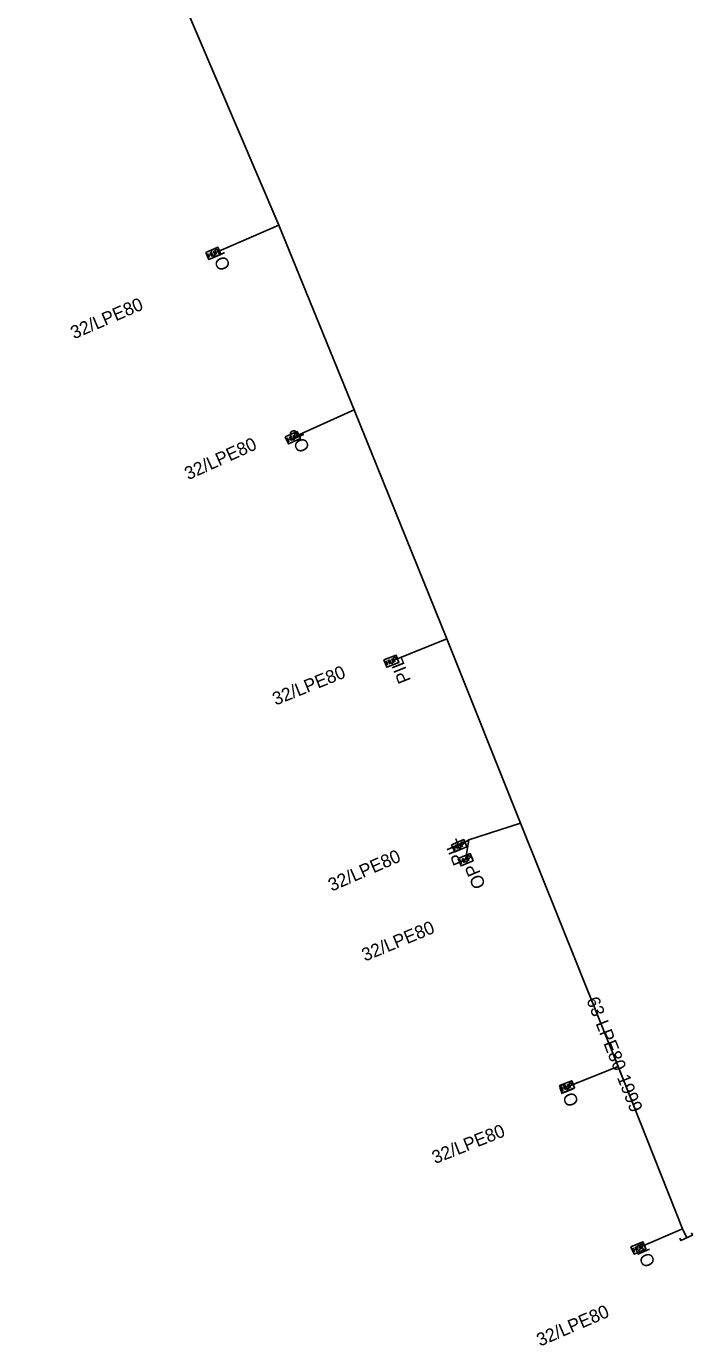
# Model space of a CAD drawing. Extents: x -762509 to -761250, y -1153000 to -1152256.
# Drawn here: x -761499.8 to -761448.8, y -1152760.9 to -1152659.8 of the extents above; entities that cross this region are included whole.
import ezdxf

# ---------------------------------------------------------------- set-up
doc = ezdxf.new("R2010")
doc.units = 0
for name, color, linetype in [('Vrstva 21', 7, 'Continuous'), ('Vrstva 23', 7, 'Continuous'), ('Vrstva 31', 7, 'Continuous'), ('Vrstva 32', 7, 'Continuous')]:
    doc.layers.add(name, color=color, linetype=linetype)

msp = doc.modelspace()

# ---------------------------------------------------------------- linework, layer by layer
at = {"layer": 'Vrstva 21'}
msp.add_lwpolyline([(-761499.83, -1152629.35), (-761499.74, -1152629.64), (-761498.8, -1152631.67), (-761497.58, -1152634.96), (-761489.98, -1152652.74), (-761480.49, -1152675), (-761474.71, -1152689.15), (-761467.61, -1152706.71), (-761461.95, -1152720.82), (-761454.47, -1152739.47), (-761449.55, -1152751.92), (-761449.22, -1152752.61)], dxfattribs=at)
at = {"layer": 'Vrstva 23'}
msp.add_lwpolyline([(-761449.757, -1152752.646), (-761449.671, -1152752.826), (-761448.769, -1152752.395), (-761448.855, -1152752.214)], dxfattribs=at)
at = {"layer": 'Vrstva 31'}
for points in [[(-761480.49, -1152675), (-761485.5, -1152677.16)], [(-761474.71, -1152689.15), (-761479.41, -1152691.28)], [(-761467.61, -1152706.71), (-761471.85, -1152708.41)], [(-761461.95, -1152720.82), (-761465.92, -1152722.1)], [(-761465.93, -1152722.1), (-761466.66, -1152722.56)], [(-761465.92, -1152722.1), (-761466.17, -1152723.63)], [(-761454.47, -1152739.47), (-761458.39, -1152741.03)], [(-761449.55, -1152751.92), (-761452.92, -1152753.38)]]:
    msp.add_lwpolyline(points, dxfattribs=at)
at = {"layer": 'Vrstva 32'}
for p, q in [((-761485.937, -1152677.158), (-761485.798, -1152677.479)), ((-761485.872, -1152677.309), (-761485.687, -1152677.23)), ((-761485.614, -1152677.399), (-761485.752, -1152677.078)), ((-761485.247, -1152677.241), (-761485.386, -1152676.92)), ((-761479.847, -1152691.286), (-761479.702, -1152691.605)), ((-761479.779, -1152691.436), (-761479.596, -1152691.353)), ((-761479.519, -1152691.522), (-761479.664, -1152691.203)), ((-761479.156, -1152691.357), (-761479.3, -1152691.038)), ((-761472.287, -1152708.396), (-761472.156, -1152708.721)), ((-761472.225, -1152708.549), (-761472.039, -1152708.475)), ((-761471.97, -1152708.646), (-761472.1, -1152708.321)), ((-761471.599, -1152708.498), (-761471.73, -1152708.173)), ((-761467.096, -1152722.553), (-761466.961, -1152722.876)), ((-761467.033, -1152722.705), (-761466.847, -1152722.628)), ((-761466.776, -1152722.798), (-761466.911, -1152722.475)), ((-761466.408, -1152722.644), (-761466.543, -1152722.322)), ((-761466.606, -1152723.624), (-761466.47, -1152723.946)), ((-761466.542, -1152723.776), (-761466.357, -1152723.698)), ((-761466.285, -1152723.868), (-761466.421, -1152723.546)), ((-761465.917, -1152723.713), (-761466.053, -1152723.391)), ((-761458.51, -1152741.266), (-761458.639, -1152740.941)), ((-761458.139, -1152741.119), (-761458.268, -1152740.794)), ((-761458.826, -1152741.015), (-761458.697, -1152741.341)), ((-761458.765, -1152741.169), (-761458.578, -1152741.094)), ((-761453.357, -1152753.378), (-761453.218, -1152753.699)), ((-761453.291, -1152753.53), (-761453.107, -1152753.45)), ((-761453.033, -1152753.619), (-761453.172, -1152753.298)), ((-761452.667, -1152753.461), (-761452.806, -1152753.14))]:
    msp.add_line(p, q, dxfattribs=at)
for points in [[(-761486.078, -1152677.082), (-761485.16, -1152676.686), (-761484.922, -1152677.237), (-761485.841, -1152677.633), (-761486.078, -1152677.082)], [(-761485.661, -1152677.039), (-761485.562, -1152677.269), (-761485.53, -1152677.309), (-761485.488, -1152677.327), (-761485.443, -1152677.326), (-761485.416, -1152677.314), (-761485.384, -1152677.282), (-761485.371, -1152677.24), (-761485.377, -1152677.19), (-761485.477, -1152676.959)], [(-761485.386, -1152676.92), (-761485.267, -1152676.869), (-761485.221, -1152676.868), (-761485.201, -1152676.876), (-761485.175, -1152676.901), (-761485.155, -1152676.947), (-761485.155, -1152676.983), (-761485.163, -1152677.003), (-761485.194, -1152677.036), (-761485.314, -1152677.087)], [(-761479.989, -1152691.213), (-761479.079, -1152690.8), (-761478.831, -1152691.347), (-761479.742, -1152691.76), (-761479.989, -1152691.213)], [(-761479.573, -1152691.162), (-761479.47, -1152691.391), (-761479.437, -1152691.429), (-761479.395, -1152691.447), (-761479.35, -1152691.445), (-761479.323, -1152691.433), (-761479.292, -1152691.4), (-761479.279, -1152691.358), (-761479.287, -1152691.308), (-761479.39, -1152691.079)], [(-761479.3, -1152691.038), (-761479.182, -1152690.984), (-761479.137, -1152690.983), (-761479.116, -1152690.991), (-761479.09, -1152691.015), (-761479.069, -1152691.061), (-761479.068, -1152691.097), (-761479.075, -1152691.117), (-761479.107, -1152691.15), (-761479.225, -1152691.204)], [(-761472.426, -1152708.317), (-761471.498, -1152707.945), (-761471.274, -1152708.502), (-761472.203, -1152708.874), (-761472.426, -1152708.317)], [(-761472.008, -1152708.285), (-761471.915, -1152708.518), (-761471.883, -1152708.558), (-761471.842, -1152708.577), (-761471.797, -1152708.577), (-761471.77, -1152708.566), (-761471.737, -1152708.535), (-761471.723, -1152708.493), (-761471.728, -1152708.443), (-761471.821, -1152708.21)], [(-761471.73, -1152708.173), (-761471.609, -1152708.125), (-761471.564, -1152708.125), (-761471.544, -1152708.134), (-761471.518, -1152708.159), (-761471.5, -1152708.206), (-761471.501, -1152708.242), (-761471.509, -1152708.262), (-761471.541, -1152708.294), (-761471.662, -1152708.342)], [(-761467.237, -1152722.476), (-761466.314, -1152722.09), (-761466.083, -1152722.644), (-761467.005, -1152723.03), (-761467.237, -1152722.476)], [(-761466.819, -1152722.437), (-761466.723, -1152722.669), (-761466.691, -1152722.709), (-761466.65, -1152722.727), (-761466.604, -1152722.727), (-761466.577, -1152722.715), (-761466.545, -1152722.684), (-761466.531, -1152722.642), (-761466.537, -1152722.591), (-761466.634, -1152722.36)], [(-761466.543, -1152722.322), (-761466.423, -1152722.271), (-761466.377, -1152722.271), (-761466.357, -1152722.28), (-761466.332, -1152722.305), (-761466.313, -1152722.351), (-761466.313, -1152722.387), (-761466.32, -1152722.407), (-761466.353, -1152722.439), (-761466.473, -1152722.489)], [(-761466.747, -1152723.548), (-761465.825, -1152723.159), (-761465.592, -1152723.712), (-761466.514, -1152724.1), (-761466.747, -1152723.548)], [(-761466.33, -1152723.507), (-761466.232, -1152723.739), (-761466.2, -1152723.778), (-761466.159, -1152723.797), (-761466.114, -1152723.796), (-761466.087, -1152723.785), (-761466.055, -1152723.753), (-761466.041, -1152723.711), (-761466.047, -1152723.661), (-761466.144, -1152723.429)], [(-761466.053, -1152723.391), (-761465.933, -1152723.34), (-761465.888, -1152723.34), (-761465.868, -1152723.349), (-761465.842, -1152723.374), (-761465.823, -1152723.42), (-761465.823, -1152723.455), (-761465.831, -1152723.476), (-761465.863, -1152723.508), (-761465.982, -1152723.559)], [(-761458.965, -1152740.936), (-761458.036, -1152740.567), (-761457.814, -1152741.124), (-761458.743, -1152741.494), (-761458.965, -1152740.936)], [(-761458.547, -1152740.905), (-761458.454, -1152741.138), (-761458.423, -1152741.178), (-761458.382, -1152741.197), (-761458.337, -1152741.198), (-761458.31, -1152741.187), (-761458.277, -1152741.156), (-761458.263, -1152741.114), (-761458.268, -1152741.063), (-761458.36, -1152740.83)], [(-761458.268, -1152740.794), (-761458.148, -1152740.746), (-761458.102, -1152740.746), (-761458.083, -1152740.755), (-761458.057, -1152740.781), (-761458.039, -1152740.827), (-761458.04, -1152740.863), (-761458.048, -1152740.883), (-761458.08, -1152740.915), (-761458.201, -1152740.963)], [(-761453.498, -1152753.303), (-761452.581, -1152752.906), (-761452.342, -1152753.456), (-761453.26, -1152753.854), (-761453.498, -1152753.303)], [(-761452.806, -1152753.14), (-761452.687, -1152753.088), (-761452.642, -1152753.087), (-761452.622, -1152753.096), (-761452.596, -1152753.12), (-761452.576, -1152753.166), (-761452.576, -1152753.202), (-761452.583, -1152753.223), (-761452.615, -1152753.255), (-761452.734, -1152753.307)], [(-761453.082, -1152753.259), (-761452.982, -1152753.489), (-761452.95, -1152753.529), (-761452.908, -1152753.547), (-761452.863, -1152753.545), (-761452.836, -1152753.534), (-761452.804, -1152753.502), (-761452.791, -1152753.46), (-761452.797, -1152753.409), (-761452.897, -1152753.179)]]:
    msp.add_lwpolyline(points, dxfattribs=at)

# ---------------------------------------------------------------- texts
at = {"layer": 'Vrstva 21'}
msp.add_text('63-LPE80-1999', height=1, rotation=291.56297, dxfattribs=at).set_placement((-761456.93, -1152734.37))
at = {"layer": 'Vrstva 31'}
for rotation, p in [(23.3227, (-761496.18, -1152683.75)), (23.3227, (-761496.18, -1152683.75)), (24.37963, (-761487.43, -1152694.55)), (24.37963, (-761487.43, -1152694.55)), (21.84799, (-761480.73, -1152711.82)), (21.84799, (-761480.73, -1152711.82)), (23.63506, (-761476.43, -1152726.08)), (23.63506, (-761476.43, -1152726.08)), (22.43629, (-761473.88, -1152731.44)), (22.43629, (-761473.88, -1152731.44)), (21.70054, (-761468.51, -1152746.96)), (21.70054, (-761468.51, -1152746.96)), (23.42392, (-761460.46, -1152760.95)), (23.42392, (-761460.46, -1152760.95))]:
    msp.add_text('32/LPE80', height=1, rotation=rotation, dxfattribs=at).set_placement(p)
at = {"layer": 'Vrstva 32'}
for s, rotation, p in [('OP', 113.3227, (-761484.15, -1152678.21)), ('OP', 113.3227, (-761484.15, -1152678.21)), ('OP', 114.37963, (-761478.07, -1152692.13)), ('OP', 114.37963, (-761478.07, -1152692.13)), ('PIL', 111.84799, (-761470.34, -1152709.88)), ('PIL', 111.84799, (-761470.34, -1152709.88)), ('PIL', 112.6879, (-761466.12, -1152723.8)), ('PIL', 112.6879, (-761466.12, -1152723.8)), ('OP', 112.86026, (-761464.6, -1152725.61)), ('OP', 112.86026, (-761464.6, -1152725.61)), ('OP', 111.70054, (-761457.46, -1152742.31)), ('OP', 111.70054, (-761457.46, -1152742.31)), ('OP', 113.42392, (-761451.59, -1152754.59)), ('OP', 113.42392, (-761451.59, -1152754.59))]:
    msp.add_text(s, height=1, rotation=rotation, dxfattribs=at).set_placement(p)

doc.saveas('drawing.dxf')
